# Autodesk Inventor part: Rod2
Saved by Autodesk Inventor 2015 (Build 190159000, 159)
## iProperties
Created: 2015-04
Part Number: Rod2
Material: Generic
Document SubType Name: Modeling
Designer: Gabriel Cabellos
Density: 1 g/cm^3
Appearance: Default
Author: Gabriel Cabellos
Sending System: SolidWorks 2011
Last Author: Pets
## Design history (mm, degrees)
node "Rod2.ipt1"
node "Mirror1"
node "Base1"
